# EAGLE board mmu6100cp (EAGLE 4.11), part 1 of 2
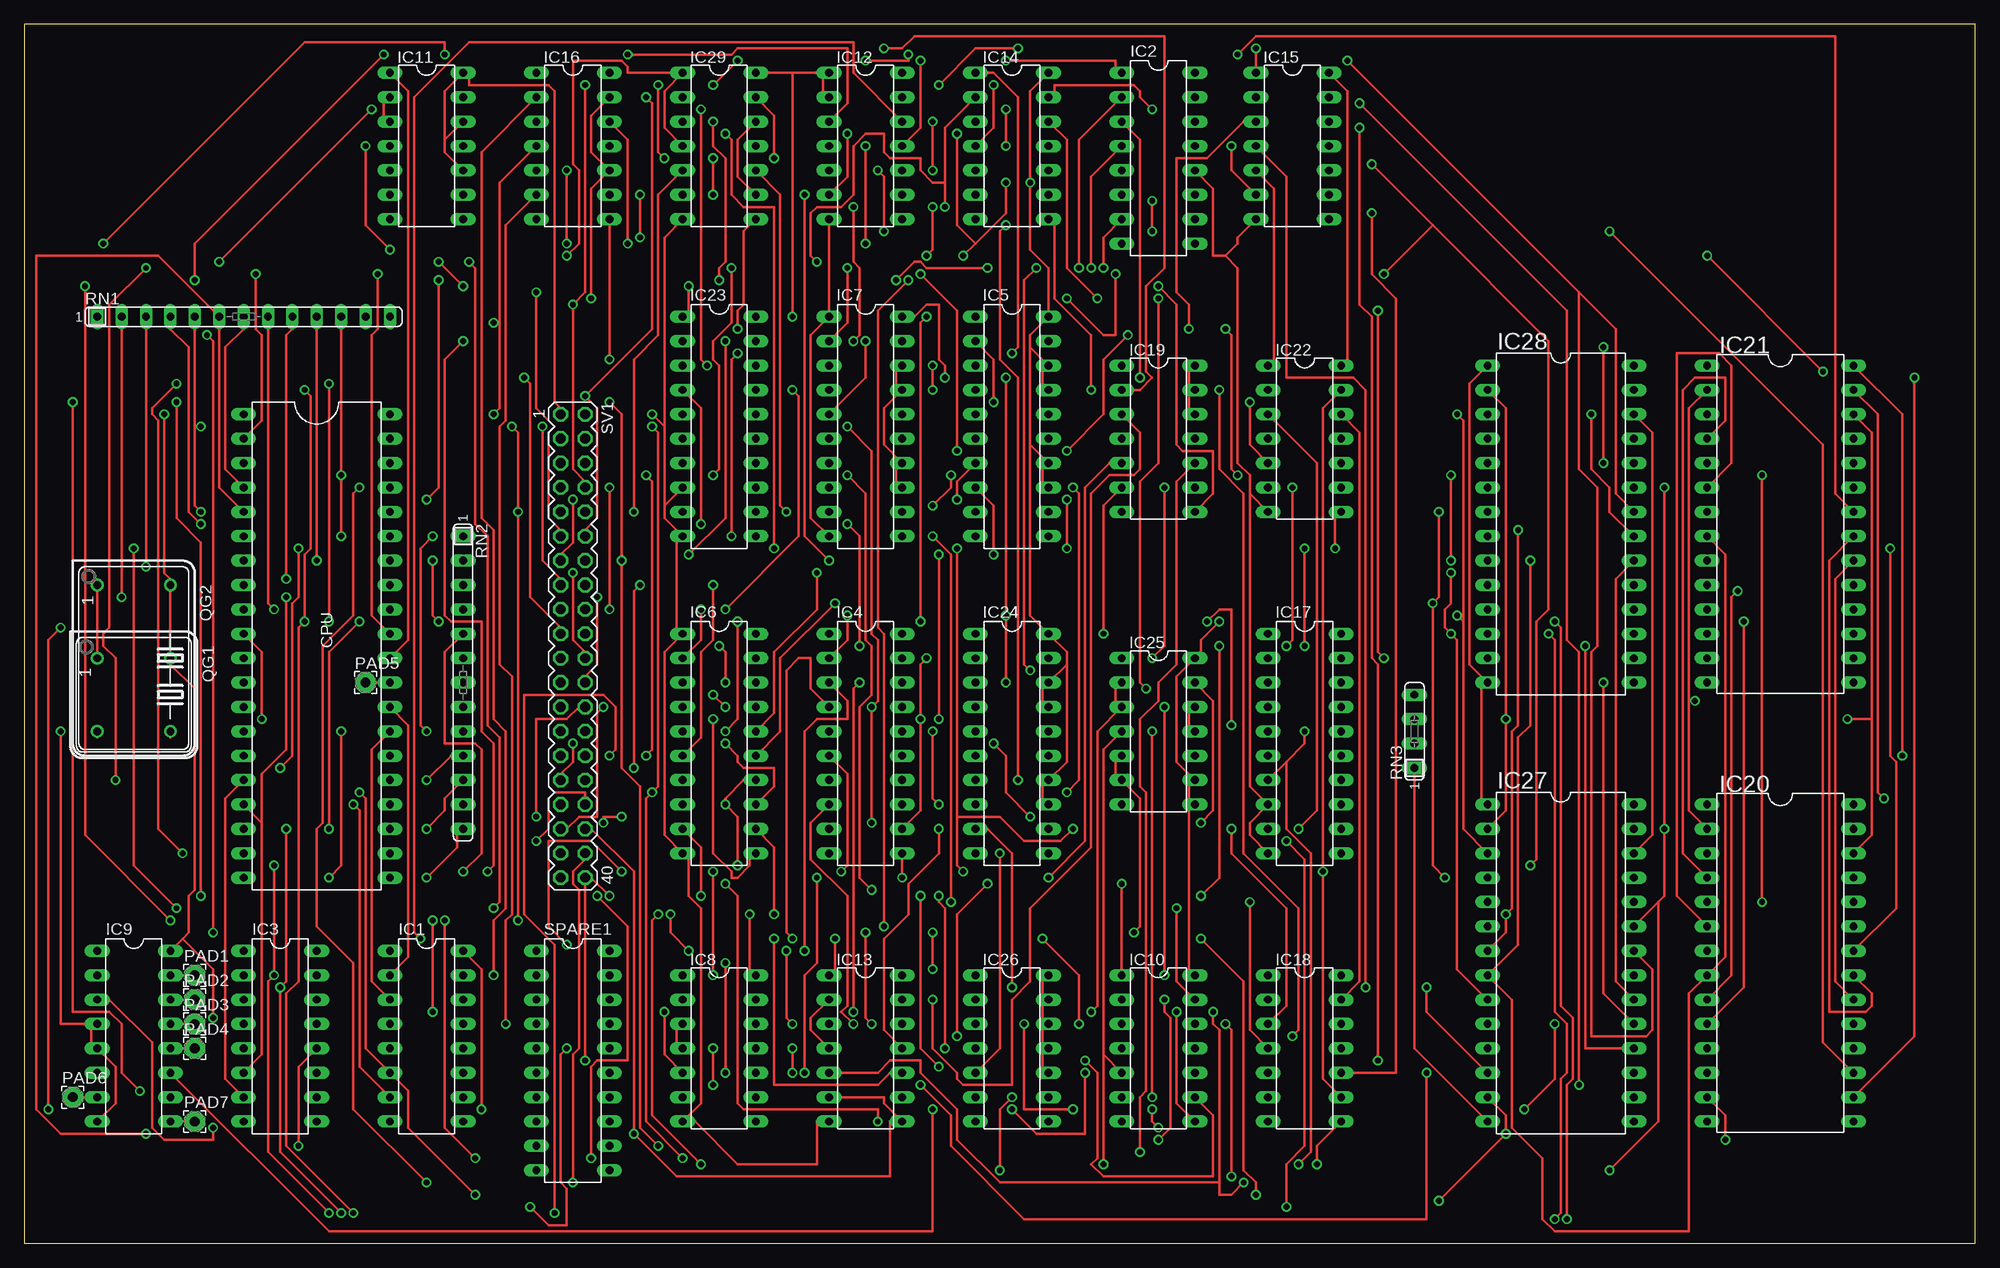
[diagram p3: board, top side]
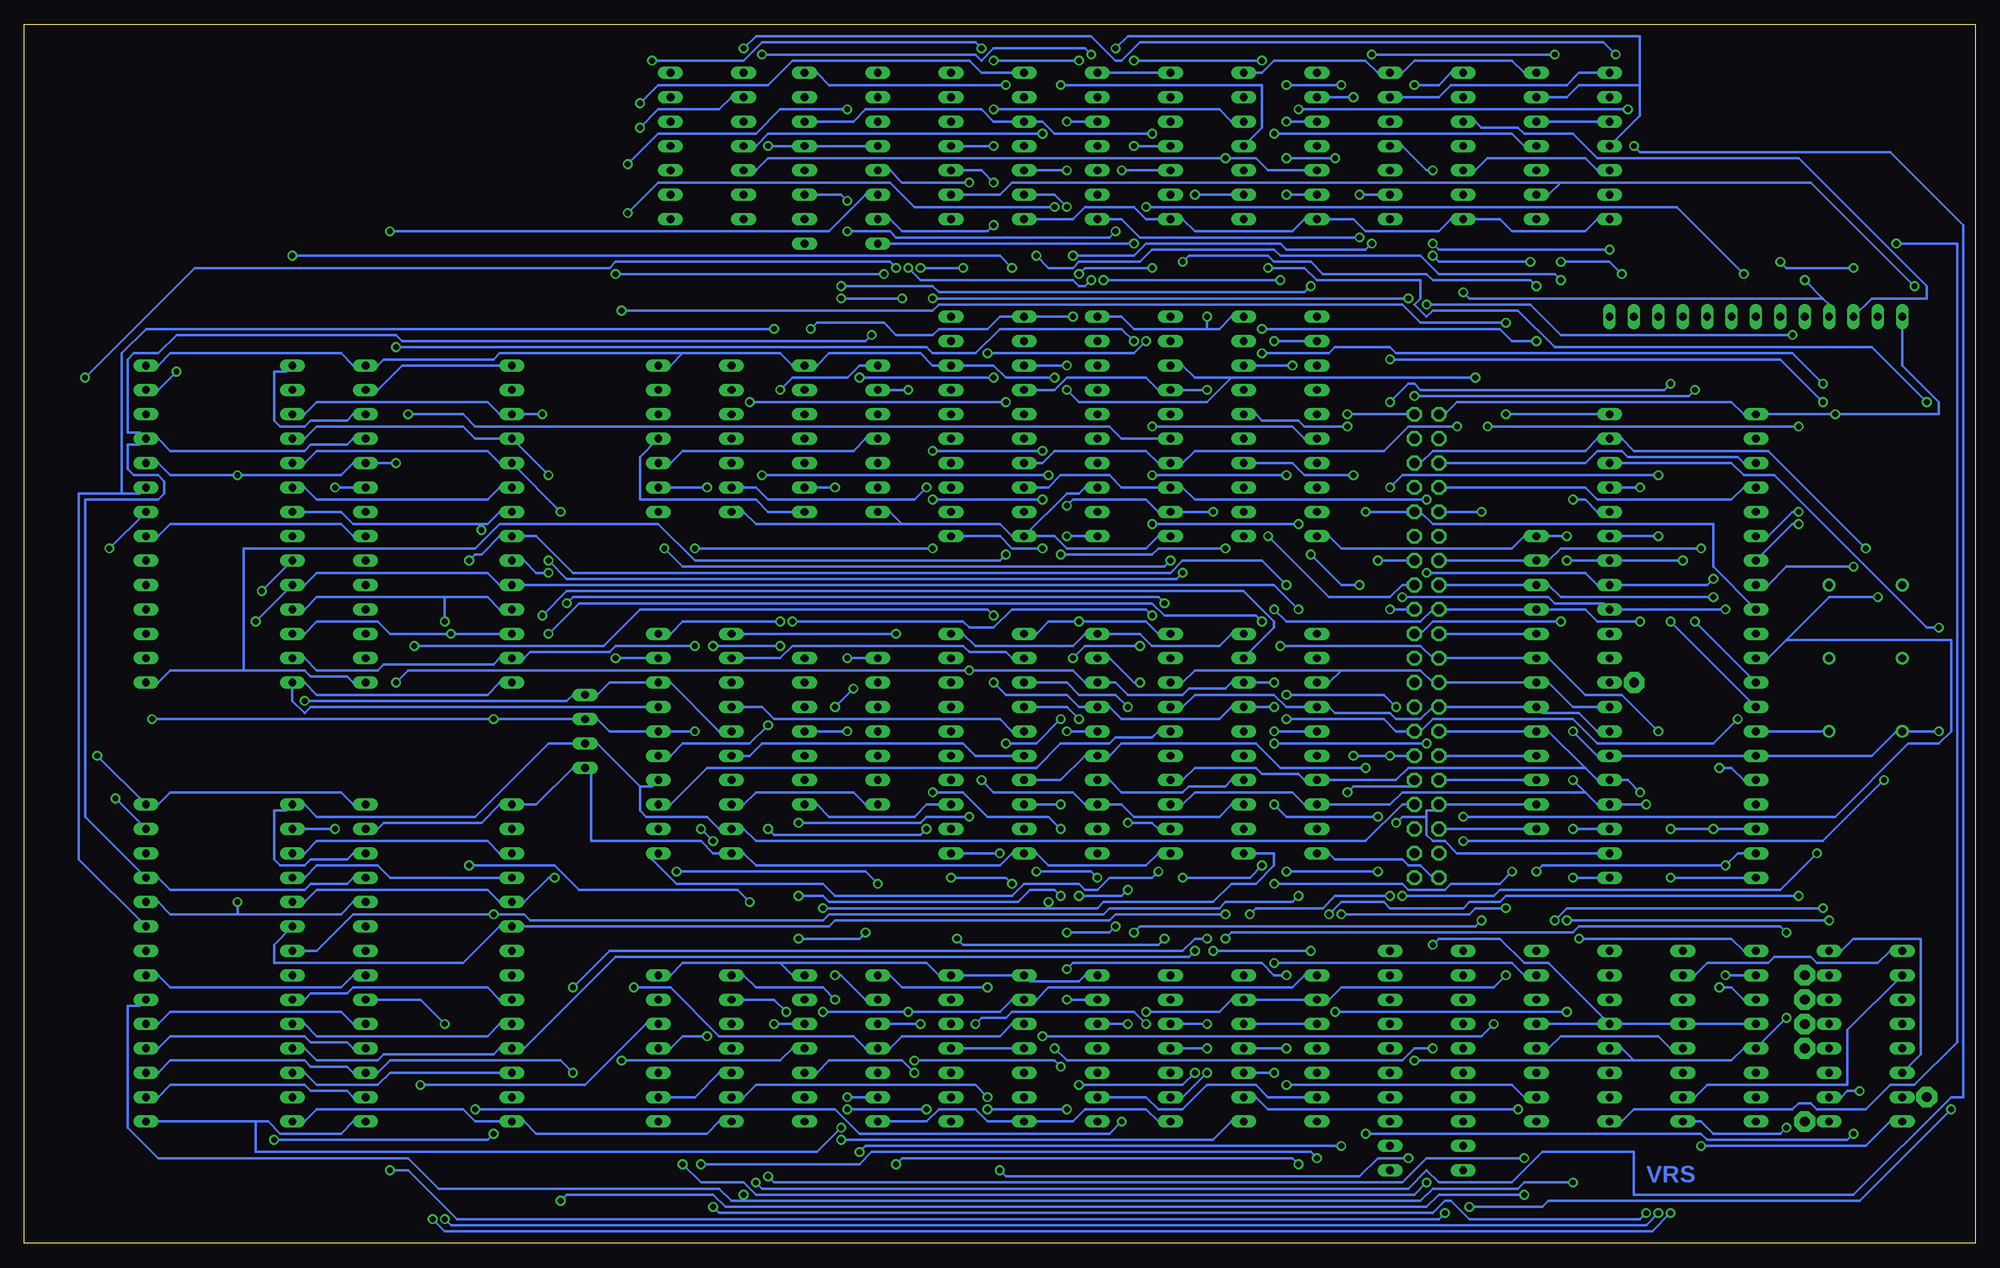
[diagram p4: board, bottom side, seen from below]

Size 203.2 x 127 mm. Coordinates in mm from the lower left corner, seen from the top.
Outline: 0,0 203.2,0 203.2,127 0,127 0,0
Copper layers (1*16): Top 0.035mm / dielectric 1.5mm / Bottom 0.035mm
Design rules "8mils": minimum track width 10mil, minimum drill 24mil, track to track 8mil, track to pad 8mil, pad to pad 8mil, via to via 8mil, smd to smd 8mil, copper to edge 40mil, drill to drill 10mil, minimum pad ring 10mil, minimum via ring 8mil, stop-mask expansion 0mil, vias tented up to drill 0mil, thermal gap 10mil

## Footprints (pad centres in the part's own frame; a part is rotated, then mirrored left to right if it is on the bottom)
DIL40 = drill 0.813 long: 1 -24.13,-7.62; 2 -21.59,-7.62; 3 -19.05,-7.62; 4 -16.51,-7.62; 5 -13.97,-7.62; 6 -11.43,-7.62; 7 -8.89,-7.62; 8 -6.35,-7.62; 9 -3.81,-7.62; 10 -1.27,-7.62; 11 1.27,-7.62; 12 3.81,-7.62; 13 6.35,-7.62; 14 8.89,-7.62; 15 11.43,-7.62; 16 13.97,-7.62; 17 16.51,-7.62; 18 19.05,-7.62; 19 21.59,-7.62; 20 24.13,-7.62; 21 24.13,7.62; 22 21.59,7.62; 23 19.05,7.62; 24 16.51,7.62; 25 13.97,7.62; 26 11.43,7.62; 27 8.89,7.62; 28 6.35,7.62; 29 3.81,7.62; 30 1.27,7.62; 31 -1.27,7.62; 32 -3.81,7.62; 33 -6.35,7.62; 34 -8.89,7.62; 35 -11.43,7.62; 36 -13.97,7.62; 37 -16.51,7.62; 38 -19.05,7.62; 39 -21.59,7.62; 40 -24.13,7.62
DIL16 = drill 0.813 long: 1 -8.89,-3.81; 2 -6.35,-3.81; 3 -3.81,-3.81; 4 -1.27,-3.81; 5 1.27,-3.81; 6 3.81,-3.81; 7 6.35,-3.81; 8 8.89,-3.81; 9 8.89,3.81; 10 6.35,3.81; 11 3.81,3.81; 12 1.27,3.81; 13 -1.27,3.81; 14 -3.81,3.81; 15 -6.35,3.81; 16 -8.89,3.81
DIL20 = drill 0.813 long: 1 -11.43,-3.81; 2 -8.89,-3.81; 3 -6.35,-3.81; 4 -3.81,-3.81; 5 -1.27,-3.81; 6 1.27,-3.81; 7 3.81,-3.81; 8 6.35,-3.81; 9 8.89,-3.81; 10 11.43,-3.81; 11 11.43,3.81; 12 8.89,3.81; 13 6.35,3.81; 14 3.81,3.81; 15 1.27,3.81; 16 -1.27,3.81; 17 -3.81,3.81; 18 -6.35,3.81; 19 -8.89,3.81; 20 -11.43,3.81
DIL14 = drill 0.813 long: 1 -7.62,-3.81; 2 -5.08,-3.81; 3 -2.54,-3.81; 4 0,-3.81; 5 2.54,-3.81; 6 5.08,-3.81; 7 7.62,-3.81; 8 7.62,3.81; 9 5.08,3.81; 10 2.54,3.81; 11 0,3.81; 12 -2.54,3.81; 13 -5.08,3.81; 14 -7.62,3.81
DIL28-6 = drill 0.813 long: 1 -16.51,-7.62; 2 -13.97,-7.62; 3 -11.43,-7.62; 4 -8.89,-7.62; 5 -6.35,-7.62; 6 -3.81,-7.62; 7 -1.27,-7.62; 8 1.27,-7.62; 9 3.81,-7.62; 10 6.35,-7.62; 11 8.89,-7.62; 12 11.43,-7.62; 13 13.97,-7.62; 14 16.51,-7.62; 15 16.51,7.62; 16 13.97,7.62; 17 11.43,7.62; 18 8.89,7.62; 19 6.35,7.62; 20 3.81,7.62; 21 1.27,7.62; 22 -1.27,7.62; 23 -3.81,7.62; 24 -6.35,7.62; 25 -8.89,7.62; 26 -11.43,7.62; 27 -13.97,7.62; 28 -16.51,7.62
DIL28 = drill 0.813 long: 1 -16.51,-7.62; 2 -13.97,-7.62; 3 -11.43,-7.62; 4 -8.89,-7.62; 5 -6.35,-7.62; 6 -3.81,-7.62; 7 -1.27,-7.62; 8 1.27,-7.62; 9 3.81,-7.62; 10 6.35,-7.62; 11 8.89,-7.62; 12 11.43,-7.62; 13 13.97,-7.62; 14 16.51,-7.62; 15 16.51,7.62; 16 13.97,7.62; 17 11.43,7.62; 18 8.89,7.62; 19 6.35,7.62; 20 3.81,7.62; 21 1.27,7.62; 22 -1.27,7.62; 23 -3.81,7.62; 24 -6.35,7.62; 25 -8.89,7.62; 26 -11.43,7.62; 27 -13.97,7.62; 28 -16.51,7.62
2,15/1,0 = drill 1.016 pad 2.159 octagon: 1 0,0
DIL08S = drill 0.813 round: 1 -3.81,-3.81; 4 3.81,-3.81; 5 3.81,3.81; 8 -3.81,3.81
DIL14S = drill 0.813 round: 1 -7.62,-3.81; 7 7.62,-3.81; 8 7.62,3.81; 14 -7.62,3.81
SIL13 = drill 0.813 long: 1 -15.24,0; 2 -12.7,0; 3 -10.16,0; 4 -7.62,0; 5 -5.08,0; 6 -2.54,0; 7 0,0; 8 2.54,0; 9 5.08,0; 10 7.62,0; 11 10.16,0; 12 12.7,0; 13 15.24,0
SIL4 = drill 0.813 long: 1 -3.81,0; 2 -1.27,0; 3 1.27,0; 4 3.81,0
MA20-2 = drill 1.016 octagon: 1 -24.13,-1.27; 2 -24.13,1.27; 3 -21.59,-1.27; 4 -21.59,1.27; 5 -19.05,-1.27; 6 -19.05,1.27; 7 -16.51,-1.27; 8 -16.51,1.27; 9 -13.97,-1.27; 10 -13.97,1.27; 11 -11.43,-1.27; 12 -11.43,1.27; 13 -8.89,-1.27; 14 -8.89,1.27; 15 -6.35,-1.27; 16 -6.35,1.27; 17 -3.81,-1.27; 18 -3.81,1.27; 19 -1.27,-1.27; 20 -1.27,1.27; 21 1.27,-1.27; 22 1.27,1.27; 23 3.81,-1.27; 24 3.81,1.27; 25 6.35,-1.27; 26 6.35,1.27; 27 8.89,-1.27; 28 8.89,1.27; 29 11.43,-1.27; 30 11.43,1.27; 31 13.97,-1.27; 32 13.97,1.27; 33 16.51,-1.27; 34 16.51,1.27; 35 19.05,-1.27; 36 19.05,1.27; 37 21.59,-1.27; 38 21.59,1.27; 39 24.13,-1.27; 40 24.13,1.27

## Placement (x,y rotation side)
CPU  IM6100  [DIL40]  30.48,62.23 270 top
IC1  74LS75N  [DIL16]  41.91,21.59 270 top
IC2  74LS75N  [DIL16]  118.11,113.03 270 top
IC3  74LS75N  [DIL16]  26.67,21.59 270 top
IC4  74LS273N  [DIL20]  87.63,52.07 270 top
IC5  74LS273N  [DIL20]  102.87,85.09 270 top
IC6  74LS373N  [DIL20]  72.39,52.07 270 top
IC7  74LS373N  [DIL20]  87.63,85.09 270 top
IC8  74LS10N  [DIL14]  72.39,20.32 270 top
IC9  74HCT138N  [DIL16]  11.43,21.59 270 top
IC10  74HCT00N  [DIL14]  118.11,20.32 270 top
IC11  74LS74N  [DIL14]  41.91,114.3 270 top
IC12  74LS30N  [DIL14]  87.63,114.3 270 top
IC13  7407N  [DIL14]  87.63,20.32 270 top
IC14  74LS10N  [DIL14]  102.87,114.3 270 top
IC15  74HCT08N  [DIL14]  132.08,114.3 270 top
IC16  74LS32N  [DIL14]  57.15,114.3 270 top
IC17  74LS241N  [DIL20]  133.35,52.07 270 top
IC18  74LS32N  [DIL14]  133.35,20.32 270 top
IC19  74LS32N  [DIL14]  118.11,83.82 270 top
IC20  62256  [DIL28-6]  182.88,29.21 270 top
IC21  62256  [DIL28-6]  182.88,74.93 270 top
IC22  74HCT04N  [DIL14]  133.35,83.82 270 top
IC23  74LS241N  [DIL20]  72.39,85.09 270 top
IC24  74LS273N  [DIL20]  102.87,52.07 270 top
IC25  74HCT02N  [DIL14]  118.11,53.34 270 top
IC26  74LS74N  [DIL14]  102.87,20.32 270 top
IC27  27512  [DIL28]  160.02,29.21 270 top
IC28  27512  [DIL28]  160.02,74.93 270 top
IC29  74HCT00N  [DIL14]  72.39,114.3 270 top
PAD1  [2,15/1,0]  17.78,27.94 0 top
PAD2  [2,15/1,0]  17.78,25.4 0 top
PAD3  [2,15/1,0]  17.78,22.86 0 top
PAD4  [2,15/1,0]  17.78,20.32 0 top
PAD5  [2,15/1,0]  35.56,58.42 0 top
PAD6  [2,15/1,0]  5.08,15.24 0 top
PAD7  [2,15/1,0]  17.78,12.7 0 top
QG1  [DIL08S]  11.43,57.15 270 top
QG2  [DIL14S]  11.43,60.96 270 top
RN1  100K  [SIL13]  22.86,96.52 0 top
RN2  100K  [SIL13]  45.72,58.42 270 top
RN3  100K  [SIL4]  144.78,53.34 90 top
SPARE1  [DIL20]  57.15,19.05 270 top
SV1  [MA20-2]  57.15,62.23 270 top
